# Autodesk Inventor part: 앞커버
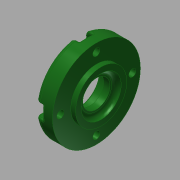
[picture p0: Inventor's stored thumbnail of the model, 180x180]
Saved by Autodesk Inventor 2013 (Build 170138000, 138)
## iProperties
Created: 2015-11
Part Number: 앞커버
Material: 알루미늄 6061
Document SubType Name: Modeling
Designer: mduedu
Density: 1 g/cm^3
Author: mduedu
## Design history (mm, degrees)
sketch "스케치1"
  geometry: L1 (-7, 0)-(7, 0); L2 (-7, 0)-(-7, 27.5); L3 (-7, 27.5)-(4, 27.5); L4 (4, 27.5)-(4, 16); L5 (4, 16)-(7, 16); L6 (7, 16)-(7, 0); 2 further points
  constraints: 12 end point, 3 perpendicular, 2 parallel, 1 coincident, 1 horizontal, 1 midpoint
  dimensions: "d0" = 14 distance of L1.start L1.end; "d1" = 55 diameter of L3 L1; "d2" = 3 distance of L4.end L5.end; "d3" = 32 diameter of L5 L1
revolve "회전1" sketch "스케치1" stored, may be unused: angle "d4" = 90 deg
hole "구멍1" diameter "d7" = 25; stored, may be unused: countersink angle "d11" = 90 deg, drill point angle "d13" = 0 deg; dims "d5" = 10, "d6" = 10, "d8" = 6, "d9" = 4, "d10" = 2, "d12" = 3
hole "구멍2" diameter "d16" = 25; stored, may be unused: countersink angle "d20" = 90 deg, drill point angle "d22" = 0 deg; dims "d17" = 6, "d18" = 4, "d19" = 2, "d21" = 7, "d63" = 10, "d64" = 10
hole "구멍3" diameter "d25" = 17; stored, may be unused: countersink angle "d29" = 90 deg, drill point angle "d31" = 0 deg; dims "d23" = 10, "d24" = 10, "d26" = 6, "d27" = 4, "d28" = 2, "d30" = 4.2
chamfer "모따기1" distance "d32" = 0.6; stored, may be unused: second distance "d33" = 2, angle "d34" = 30 deg
fillet "모깎기1" dims "d35" = 0.3
fillet "모깎기2" dims "d36" = 3
fillet "모깎기3" dims "d37" = 3
sketch "스케치2" dims "d39" = 45
  geometry: C1 r 12.846 at (0, 0) reference; C2 r 24.5 at (0, 0) reference; 6 further points
  constraints: 2 vertical alignment, 1 coincident, 7 other
  dimensions: "d42" = 360 deg dimension on point (0, 0) point (0, 22.5) (derived)
sketch "스케치3"
  geometry: 8 further points
  constraints: 4 coincident
hole "구멍4" sketch "스케치3" at (-22.5, 0), (0, -22.5), (22.5, 0), (0, 22.5) diameter "d44" = 4.5; stored, may be unused: countersink angle "d48" = 90 deg, drill point angle "d50" = 0 deg; dims "d45" = 6, "d46" = 8, "d47" = 4.6, "d49" = 8
sketch "스케치4"
  geometry: L1 (-4, 0)-(-4, -4.708); L2 (4, 0)-(4, -4.708); A1 r 4 centre (0, 0) between (-4, 0) and (4, 0) reference; A2 r 27.5 centre (0, 22.5) between (-4, -4.708) and (4, -4.708) reference; 3 further points
  constraints: 4 end point, 4 point on circle, 2 tangent, 1 parallel, 1 vertical
extrude "돌출1" cut sketch "스케치4" stored distance "d51" = 0; taper "d52" = 0 deg
fillet "모깎기5" dims "d56" = 0.3
fillet "모깎기6" dims "d57" = 1
node "솔리드1"
pattern_circular "원형 패턴1" dims angle "d54" = 360 deg
